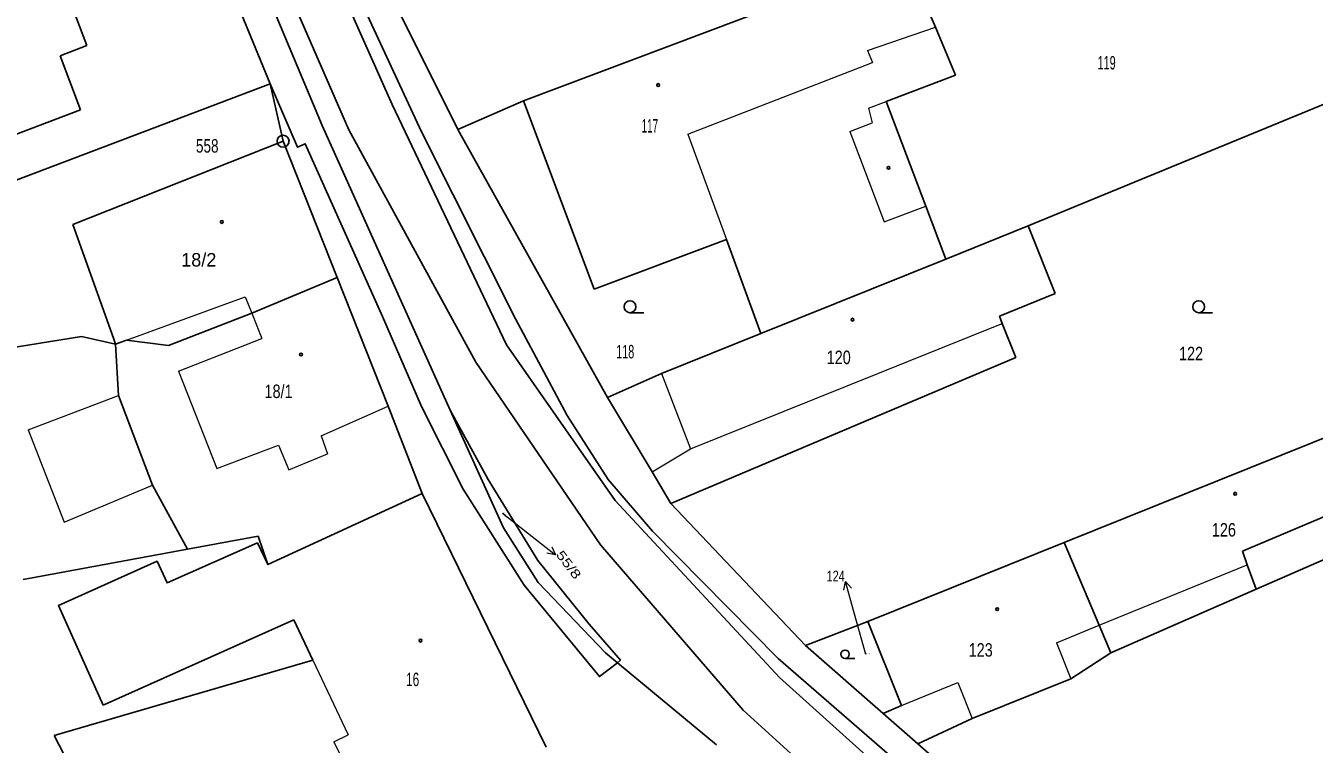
# Model space of a CAD drawing. Extents: x -592965 to -592390, y -1145071 to -1144631.
# Drawn here: x -592701.3 to -592620.1, y -1144754 to -1144708.7 of the extents above; entities that cross this region are included whole.
import ezdxf
from ezdxf.enums import TextEntityAlignment as Align

# ---------------------------------------------------------------- set-up
doc = ezdxf.new("R2010")
doc.units = 0
doc.header["$LTSCALE"] = 0.17
doc.layers.add('4', color=7, linetype='Continuous', lineweight=25)

msp = doc.modelspace()

# ---------------------------------------------------------------- linework, layer by layer
at = {"layer": '4'}
for p, q in [((-592691.66, -1144690.59), (-592680.91, -1144715.27)), ((-592687.79, -1144692.02), (-592678.19, -1144713.68)), ((-592684.18, -1144698.5), (-592676.33, -1144715.39)), ((-592645.8, -1144704.36), (-592643.94, -1144708.8)), ((-592698.59, -1144706.9), (-592697.44, -1144709.96)), ((-592643.94, -1144708.8), (-592642.67, -1144711.83)), ((-592699.12, -1144710.6), (-592697.44, -1144709.96)), ((-592699.12, -1144710.6), (-592697.83, -1144714.01)), ((-592647.05, -1144713.49), (-592642.67, -1144711.83)), ((-592638.1, -1144721.33), (-592613.93, -1144711.39)), ((-592715.29, -1144723.52), (-592685.87, -1144712.37)), ((-592669.9, -1144713.45), (-592665.45, -1144725.32)), ((-592703.44, -1144716.13), (-592697.83, -1144714.01)), ((-592678.19, -1144713.68), (-592670.98, -1144728.83)), ((-592647.05, -1144713.49), (-592644.54, -1144720.08)), ((-592680.91, -1144715.27), (-592672.91, -1144729.91)), ((-592676.33, -1144715.39), (-592670.4, -1144727.19)), ((-592674.05, -1144715.26), (-592664.6, -1144732.15)), ((-592698.32, -1144721.24), (-592685.06, -1144715.99)), ((-592644.54, -1144720.08), (-592643.27, -1144723.42)), ((-592698.32, -1144721.24), (-592695.75, -1144728.41)), ((-592643.27, -1144723.42), (-592638.1, -1144721.33)), ((-592638.1, -1144721.33), (-592636.38, -1144725.6)), ((-592665.45, -1144725.32), (-592657.11, -1144722.18)), ((-592657.11, -1144722.18), (-592654.94, -1144728.11)), ((-592654.94, -1144728.11), (-592643.27, -1144723.42)), ((-592687.03, -1144726.83), (-592681.65, -1144724.59)), ((-592639.9, -1144727.02), (-592636.38, -1144725.6)), ((-592692.29, -1144728.87), (-592687.03, -1144726.83)), ((-592670.4, -1144727.19), (-592667.16, -1144733.28)), ((-592662.315, -1144726.8), (-592663.19, -1144726.8)), ((-592639.9, -1144727.02), (-592639.72, -1144727.48)), ((-592626.465, -1144726.8), (-592627.34, -1144726.8)), ((-592639.72, -1144727.48), (-592638.86, -1144729.62)), ((-592708.3, -1144730.02), (-592697.76, -1144728.29)), ((-592697.76, -1144728.29), (-592695.62, -1144728.79)), ((-592695.75, -1144728.41), (-592695.62, -1144728.79)), ((-592695.62, -1144728.79), (-592694.94, -1144728.54)), ((-592695.62, -1144728.79), (-592695.44, -1144732.02)), ((-592694.94, -1144728.54), (-592692.29, -1144728.87)), ((-592670.98, -1144728.83), (-592664.13, -1144738.64)), ((-592661.21, -1144730.64), (-592654.94, -1144728.11)), ((-592660.62, -1144738.83), (-592638.86, -1144729.62)), ((-592672.91, -1144729.91), (-592665.05, -1144741.43)), ((-592664.6, -1144732.15), (-592661.21, -1144730.64)), ((-592695.44, -1144732.02), (-592693.29, -1144737.67)), ((-592664.6, -1144732.15), (-592661.79, -1144736.84)), ((-592635.82, -1144741.28), (-592613.27, -1144732.2)), ((-592667.16, -1144733.28), (-592664.57, -1144737.31)), ((-592661.79, -1144736.84), (-592660.62, -1144738.83)), ((-592624.58, -1144741.83), (-592611.53, -1144736.31)), ((-592693.29, -1144737.67), (-592691.09, -1144741.71)), ((-592664.57, -1144737.31), (-592661.78, -1144740.58)), ((-592664.13, -1144738.64), (-592653.76, -1144749.79)), ((-592660.62, -1144738.83), (-592652.12, -1144747.78)), ((-592691.09, -1144741.71), (-592686.62, -1144740.89)), ((-592661.78, -1144740.58), (-592653.84, -1144748.59)), ((-592701.44, -1144743.62), (-592691.09, -1144741.71)), ((-592665.05, -1144741.43), (-592656.05, -1144751.86)), ((-592648.2, -1144746.27), (-592635.82, -1144741.28)), ((-592635.82, -1144741.28), (-592633.62, -1144746.5)), ((-592684.38, -1144746.16), (-592696.41, -1144751.54)), ((-592684.38, -1144746.16), (-592683.18, -1144748.71)), ((-592652.12, -1144747.78), (-592648.2, -1144746.27)), ((-592648.2, -1144746.27), (-592646.07, -1144751.55)), ((-592652.12, -1144747.78), (-592647.23, -1144752.06)), ((-592635.41, -1144749.88), (-592632.87, -1144748.23)), ((-592699.48, -1144753.44), (-592683.18, -1144748.71)), ((-592653.84, -1144748.59), (-592645.55, -1144755.81)), ((-592649.018, -1144748.59), (-592649.63, -1144748.59)), ((-592653.76, -1144749.79), (-592640.29, -1144761.91)), ((-592641.63, -1144752.38), (-592635.41, -1144749.88)), ((-592647.23, -1144752.06), (-592646.07, -1144751.55)), ((-592656.05, -1144751.86), (-592641.63, -1144764.93)), ((-592647.23, -1144752.06), (-592645.05, -1144753.97)), ((-592645.05, -1144753.97), (-592641.63, -1144752.38)), ((-592699.48, -1144753.44), (-592694.03, -1144764.07)), ((-592645.05, -1144753.97), (-592635.75, -1144762.1))]:
    msp.add_line(p, q, dxfattribs=at)
at = {"layer": '4', "lineweight": 13}
for p, q in [((-592648.21, -1144710.27), (-592643.94, -1144708.8)), ((-592648.21, -1144710.27), (-592647.91, -1144711.04)), ((-592659.54, -1144715.54), (-592647.91, -1144711.04)), ((-592648.15, -1144713.91), (-592647.05, -1144713.49)), ((-592648.15, -1144713.91), (-592647.93, -1144714.84)), ((-592649.33, -1144715.38), (-592647.93, -1144714.84)), ((-592659.54, -1144715.54), (-592657.11, -1144722.18)), ((-592649.33, -1144715.38), (-592647.16, -1144721.08)), ((-592647.16, -1144721.08), (-592644.54, -1144720.08)), ((-592694.94, -1144728.54), (-592687.44, -1144725.8)), ((-592687.44, -1144725.8), (-592687.03, -1144726.83)), ((-592687.03, -1144726.83), (-592686.4, -1144728.42)), ((-592659.37, -1144735.39), (-592639.72, -1144727.48)), ((-592691.65, -1144730.49), (-592686.4, -1144728.42)), ((-592661.21, -1144730.64), (-592659.37, -1144735.39)), ((-592701.12, -1144734.18), (-592695.44, -1144732.02)), ((-592682.65, -1144734.56), (-592678.44, -1144732.7)), ((-592682.65, -1144734.56), (-592682.26, -1144735.7)), ((-592685.34, -1144735.14), (-592684.7, -1144736.71)), ((-592684.7, -1144736.71), (-592682.26, -1144735.7)), ((-592661.79, -1144736.84), (-592659.37, -1144735.39)), ((-592633.62, -1144746.5), (-592624.28, -1144742.7)), ((-592636.3, -1144747.6), (-592633.62, -1144746.5)), ((-592636.3, -1144747.6), (-592635.41, -1144749.88)), ((-592683.18, -1144748.71), (-592680.95, -1144753.41)), ((-592646.07, -1144751.55), (-592642.52, -1144750.11)), ((-592642.52, -1144750.11), (-592641.63, -1144752.38)), ((-592681.85, -1144753.84), (-592680.95, -1144753.41)), ((-592681.85, -1144753.84), (-592679.14, -1144759.39))]:
    msp.add_line(p, q, dxfattribs=at)
at = {"layer": '4'}
for points in [[(-592682.6, -1144715), (-592691.47, -1144693.85), (-592714.72, -1144631.04)], [(-592682.65, -1144697.93), (-592680.17, -1144702.93), (-592679.04, -1144705.21), (-592674.05, -1144715.26), (-592669.9, -1144713.45)], [(-592691.2, -1144699.44), (-592685.87, -1144712.37), (-592685.06, -1144715.99), (-592681.65, -1144724.59), (-592678.44, -1144732.7)], [(-592669.9, -1144713.45), (-592656.17, -1144708.27), (-592645.8, -1144704.36)], [(-592685.87, -1144712.37), (-592684.16, -1144716.37), (-592683.66, -1144716.15), (-592678.79, -1144727.03), (-592676.34, -1144732.71), (-592673.7, -1144737.93), (-592669.87, -1144743.97), (-592665.12, -1144749.74), (-592663.97, -1144748.86), (-592663.79, -1144748.71), (-592665.76, -1144746.44), (-592669, -1144742.41), (-592672.14, -1144737.32), (-592674.52, -1144732.94)], [(-592682.6, -1144715), (-592674.52, -1144732.94), (-592671.17, -1144740.36)], [(-592678.44, -1144732.7), (-592676.29, -1144738.2), (-592668.48, -1144754.19)], [(-592624.58, -1144741.83), (-592624.28, -1144742.7), (-592623.72, -1144744.23), (-592608.55, -1144737.6)], [(-592686.62, -1144740.89), (-592686.03, -1144742.68), (-592676.29, -1144738.2)], [(-592671.17, -1144740.36), (-592668.98, -1144743.81), (-592664.73, -1144748.23)], [(-592696.41, -1144751.54), (-592699.22, -1144745.26), (-592693, -1144742.47), (-592692.37, -1144743.83), (-592686.68, -1144741.31), (-592686.03, -1144742.68)], [(-592633.62, -1144746.5), (-592632.87, -1144748.23), (-592623.72, -1144744.23)], [(-592664.73, -1144748.23), (-592663.97, -1144748.86), (-592657.74, -1144754.03)]]:
    msp.add_lwpolyline(points, dxfattribs=at)
at = {"layer": '4', "lineweight": 13}
for points in [[(-592691.65, -1144730.49), (-592689.23, -1144736.62), (-592685.34, -1144735.14)], [(-592701.12, -1144734.18), (-592698.86, -1144740.01), (-592693.29, -1144737.67)], [(-592671.22, -1144739.44), (-592669.066, -1144741.133), (-592667.887, -1144742.06)], [(-592668.125, -1144741.554), (-592667.887, -1144742.06), (-592668.434, -1144741.948)], [(-592649.713, -1144744.289), (-592649.607, -1144743.74), (-592649.232, -1144744.155)], [(-592648.32, -1144748.34), (-592649.203, -1144745.185), (-592649.607, -1144743.74)]]:
    msp.add_lwpolyline(points, dxfattribs=at)
at = {"layer": '4'}
for centre, radius in [((-592661.41, -1144712.45), 0.0875), ((-592685.06, -1144715.99), 0.375), ((-592685.06, -1144715.99), 0.0164), ((-592646.89, -1144717.67), 0.0875), ((-592688.92, -1144721.08), 0.0875), ((-592663.19, -1144726.425), 0.375), ((-592627.34, -1144726.425), 0.375), ((-592649.16, -1144727.24), 0.0875), ((-592683.93, -1144729.44), 0.0875), ((-592625.04, -1144738.21), 0.0875), ((-592640.04, -1144745.49), 0.0875), ((-592676.39, -1144747.47), 0.0875), ((-592649.63, -1144748.3275), 0.2625)]:
    msp.add_circle(centre, radius, dxfattribs=at)

# ---------------------------------------------------------------- texts
for s, height, width, p in [('119', 0.85, 0.6, (-592633.71, -1144711.47)), ('117', 0.85, 0.55, (-592662.46, -1144715.45)), ('118', 0.85, 0.6, (-592664.06, -1144729.68)), ('120', 0.85, 0.8, (-592650.79, -1144730.04)), ('122', 0.85, 0.8, (-592628.58, -1144729.8)), ('18/1', 0.85, 0.8, (-592686.23, -1144732.18)), ('126', 0.85, 0.8, (-592626.51, -1144740.91)), ('124', 0.68, 0.75, (-592650.793, -1144743.74)), ('124', 0.1, 0.9, (-592648.32, -1144748.34)), ('123', 0.85, 0.8, (-592641.84, -1144748.48)), ('16', 0.85, 0.65, (-592677.3, -1144750.34))]:
    msp.add_text(s, height=height, dxfattribs=dict(at, width=width)).set_placement(p)
at = {"layer": '4', "width": 0.75}
msp.add_text('558', height=0.85, dxfattribs=at).set_placement((-592689.84, -1144716.71), align=Align.CENTER)
at = {"layer": '4'}
msp.add_text('18/2', height=0.85, dxfattribs=at).set_placement((-592691.48, -1144723.89))
for height, width, p in [(0.1, 1.5, (-592671.22, -1144739.44)), (0.57, 1.35, (-592667.887, -1144742.06))]:
    msp.add_text('55/8', height=height, rotation=307.117, dxfattribs=dict(at, width=width)).set_placement(p)

doc.saveas('drawing.dxf')
